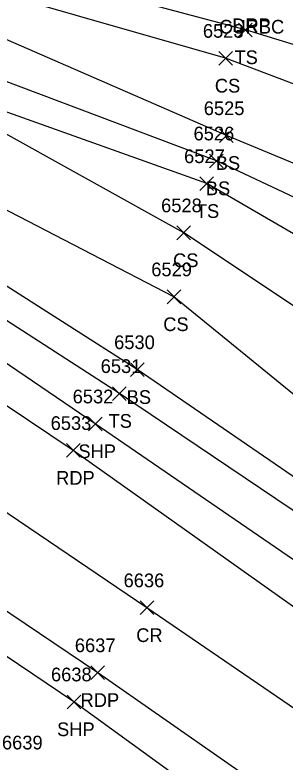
# Model space of a CAD drawing. Extents: x 1505656 to 1508446, y 700805 to 703031.
# Drawn here: x 1507720.3 to 1507759.8, y 701245.9 to 701354.9 of the extents above; entities that cross this region are included whole.
import ezdxf

# ---------------------------------------------------------------- set-up
doc = ezdxf.new("R2010")
doc.units = 0
for name, color, linetype in [('L_A', 7, 'Continuous'), ('L_I', 7, 'Continuous'), ('L_TIC', 7, 'Continuous'), ('LELB', 7, 'Continuous'), ('P_A', 7, 'Continuous'), ('P_I', 7, 'Continuous'), ('P_TIC', 7, 'Continuous'), ('PET', 7, 'Continuous'), ('PRC', 7, 'Continuous'), ('PSP', 7, 'Continuous'), ('R_A', 7, 'Continuous')]:
    doc.layers.add(name, color=color, linetype=linetype)

msp = doc.modelspace()

# ---------------------------------------------------------------- linework, layer by layer
at = {"layer": 'L_TIC'}
for points in [[(1507753.03, 701351.76), (1507755.03, 701353.76)], [(1507755.03, 701351.76), (1507753.03, 701353.76)], [(1507750.13, 701347.61), (1507752.13, 701349.61)], [(1507752.13, 701347.61), (1507750.13, 701349.61)], [(1507750.26, 701336.32), (1507752.26, 701338.32)], [(1507752.26, 701336.32), (1507750.26, 701338.32)], [(1507748.81, 701332.63), (1507750.81, 701334.63)], [(1507750.81, 701332.63), (1507748.81, 701334.63)], [(1507747.38, 701329.31), (1507749.38, 701331.31)], [(1507749.38, 701329.31), (1507747.38, 701331.31)], [(1507744.02, 701322.13), (1507746.02, 701324.13)], [(1507746.02, 701322.13), (1507744.02, 701324.13)], [(1507742.58, 701312.79), (1507744.58, 701314.79)], [(1507744.58, 701312.79), (1507742.58, 701314.79)], [(1507737.23, 701302.16), (1507739.23, 701304.16)], [(1507739.23, 701302.16), (1507737.23, 701304.16)], [(1507734.61, 701298.67), (1507736.61, 701300.67)], [(1507736.61, 701298.67), (1507734.61, 701300.67)]]:
    msp.add_lwpolyline(points, dxfattribs=at)
at = {"layer": 'LELB'}
for points in [[(1507790.41, 701341.61), (1507754.03, 701352.76), (1507708.05, 701364.97), (1507681.85, 701373.12), (1507670.48, 701378.38), (1507653.2, 701386.6), (1507647.55, 701385.55), (1507641.37, 701382.2), (1507637.8, 701373.1), (1507641.82, 701365.1)], [(1507888.34, 701276.55), (1507888.87, 701277.41), (1507874.85, 701282.09), (1507865.24, 701285.97), (1507819.75, 701304.34), (1507789.12, 701315.18), (1507749.81, 701333.63), (1507703.74, 701350.99), (1507669.93, 701363.92), (1507645.02, 701377.64), (1507646.46, 701380.37)], [(1507958.45, 701336.45), (1507943.72, 701322.98), (1507916.13, 701303.87), (1507903.31, 701294.67), (1507892.08, 701289.43), (1507877.87, 701288.47), (1507867.89, 701292.89), (1507821.41, 701310.87), (1507790.62, 701321.07), (1507785.01, 701323.39), (1507751.26, 701337.32), (1507705.7, 701357.18), (1507672.82, 701369.27), (1507646.46, 701380.37)], [(1507888.34, 701276.55), (1507871.44, 701272.97), (1507859.56, 701274.07), (1507818.82, 701298.43), (1507786.1, 701308.48), (1507748.38, 701330.31), (1507702.71, 701346.6), (1507667.51, 701360.57), (1507645.02, 701377.64)], [(1507789.2, 701334.24), (1507751.13, 701348.61), (1507707.11, 701361.23), (1507681.85, 701373.12)], [(1508013.25, 701346.1), (1507984.49, 701324.83), (1507956.47, 701302.43), (1507918.76, 701270.83), (1507904.06, 701248.78), (1507886.68, 701234.44), (1507873.56, 701226.96), (1507860, 701227.91), (1507852, 701227.74), (1507843.18, 701230.27), (1507815.13, 701253.1), (1507771.9, 701280.14), (1507738.23, 701303.16), (1507696.59, 701329.67), (1507663.2, 701353.11), (1507646.46, 701366.45)], [(1508015.05, 701343.61), (1507986.33, 701322.01), (1507960.59, 701298.46), (1507925.28, 701262.85), (1507907.53, 701244.92), (1507889.25, 701230.66), (1507874.35, 701224.63), (1507863.53, 701221.86), (1507853.81, 701222.35), (1507841.84, 701226.62), (1507812.69, 701248.41), (1507769.98, 701276.58), (1507735.61, 701299.67), (1507693.17, 701327.02), (1507661.01, 701349.45), (1507641.82, 701365.1)], [(1507916.99, 701276.14), (1507899.54, 701258.77), (1507881.72, 701245.16), (1507867.45, 701235.85), (1507848.82, 701240.61), (1507819.44, 701259.37), (1507776.79, 701286.76), (1507743.58, 701313.79), (1507698.16, 701337.22), (1507663.2, 701353.11)], [(1507891.9, 701273.68), (1507878.18, 701257.1), (1507870.06, 701251.87), (1507857.54, 701254.89), (1507821.42, 701279.67), (1507798.29, 701290.96), (1507781.81, 701298.69), (1507745.02, 701323.13), (1507702.71, 701346.6)]]:
    msp.add_lwpolyline(points, dxfattribs=at)
at = {"layer": 'P_TIC'}
for points in [[(1507731.08, 701294.24), (1507733.08, 701296.24)], [(1507733.08, 701294.24), (1507731.08, 701296.24)], [(1507727.86, 701290.36), (1507729.86, 701292.36)], [(1507729.86, 701290.36), (1507727.86, 701292.36)], [(1507738.63, 701267.4), (1507740.63, 701269.4)], [(1507740.63, 701267.4), (1507738.63, 701269.4)], [(1507731.44, 701257.92), (1507733.44, 701259.92)], [(1507733.44, 701257.92), (1507731.44, 701259.92)], [(1507727.95, 701253.66), (1507729.95, 701255.66)], [(1507729.95, 701253.66), (1507727.95, 701255.66)]]:
    msp.add_lwpolyline(points, dxfattribs=at)
at = {"layer": 'PET'}
for points in [[(1508337.31, 700875.8), (1508299.12, 700901.22), (1508243.21, 700939.46), (1508171.95, 700987.77), (1508130.48, 701015.52), (1508098, 701037.64), (1508055.47, 701066.53), (1508022.23, 701089.23), (1507988.57, 701112.23), (1507963.26, 701129.32), (1507945.8, 701141.83), (1507902.27, 701172.19), (1507883.2, 701183.96), (1507860.24, 701201.06), (1507835.12, 701217.44), (1507805.58, 701238.78), (1507763.25, 701266.99), (1507728.86, 701291.36), (1507688.43, 701318.43), (1507655.64, 701340.89)], [(1508325.47, 700853.93), (1508286.34, 700880.08), (1508228.39, 700919.42), (1508193.53, 700942.69), (1508162.03, 700964.2), (1508126.36, 700988.76), (1508069.26, 701027.69), (1508039.88, 701046.84), (1507982.91, 701086.28), (1507949.88, 701109.29), (1507927.44, 701124.58), (1507885.02, 701153.86), (1507843.8, 701182.01), (1507811.49, 701204.8), (1507770.51, 701232.43), (1507732.44, 701258.92), (1507681.2, 701293.35)]]:
    msp.add_lwpolyline(points, dxfattribs=at)
at = {"layer": 'PRC'}
msp.add_lwpolyline([(1508330.81, 700865.18), (1508292.58, 700890.76), (1508235.81, 700929.21), (1508200.17, 700953), (1508165.62, 700976.67), (1508123.91, 701005.48), (1508090.88, 701028.02), (1508048, 701056.52), (1508015.22, 701078.96), (1507981.58, 701102.27), (1507956.81, 701119), (1507935.36, 701133.83), (1507892.74, 701162.9), (1507856.87, 701187.72), (1507818.46, 701214.03), (1507776.64, 701243.14), (1507739.63, 701268.4), (1507687.66, 701303.5)], dxfattribs=at)
at = {"layer": 'PSP'}
for points in [[(1508339.2, 700878.52), (1508300.65, 700904.32), (1508290.66, 700911.25), (1508285.71, 700920.13), (1508246.94, 700946.03), (1508214.54, 700968.68), (1508208.31, 700968.43), (1508200.27, 700972.31), (1508174.14, 700990.25), (1508132.47, 701018.55), (1508100.45, 701040.48), (1508057.36, 701069.9), (1508024.07, 701092.52), (1507991.15, 701114.56), (1507965.56, 701132.67), (1507948.13, 701145), (1507904.26, 701176.52), (1507885.27, 701189.48), (1507863.62, 701204.84), (1507839.06, 701222.13), (1507808.57, 701243.06), (1507766.97, 701271.37), (1507732.08, 701295.24), (1507690.9, 701323.18)], [(1508322.11, 700849.23), (1508283.29, 700875.62), (1508225.23, 700915.4), (1508190.18, 700938.93), (1508158.85, 700960.02), (1508133.58, 700977.43), (1508108.68, 700994.35), (1508066.55, 701022.65), (1508035.75, 701043.71), (1507979.02, 701080.76), (1507948.09, 701102.19), (1507924.34, 701119.43), (1507882.16, 701148.7), (1507840.1, 701177.09), (1507807.52, 701199.39), (1507768.58, 701225.94), (1507728.95, 701254.66), (1507678.68, 701288.49)]]:
    msp.add_lwpolyline(points, dxfattribs=at)

# ---------------------------------------------------------------- texts
at = {"layer": 'L_A'}
for s, p in [('TS', (1507752.44, 701347.76)), ('CS', (1507749.57, 701343.61)), ('BS', (1507749.7, 701332.32)), ('BS', (1507748.25, 701328.63)), ('TS', (1507746.79, 701325.31)), ('CS', (1507743.46, 701318.13)), ('CS', (1507742.02, 701308.79)), ('BS', (1507736.67, 701298.16)), ('TS', (1507734.02, 701294.67))]:
    msp.add_text(s, height=2, dxfattribs=at).set_placement(p)
at = {"layer": 'L_I'}
for s, p in [('6523', (1507747.82, 701351.61)), ('6525', (1507747.95, 701340.32)), ('6526', (1507746.45, 701336.63)), ('6527', (1507745.07, 701333.31)), ('6528', (1507741.71, 701326.13)), ('6529', (1507740.27, 701316.79)), ('6530', (1507734.84, 701306.16)), ('6531', (1507732.87, 701302.67)), ('6639', (1507718.43, 701247.72))]:
    msp.add_text(s, height=2, dxfattribs=at).set_placement(p)
at = {"layer": 'P_A'}
for s, p in [('SHP', (1507729.61, 701290.24)), ('RDP', (1507726.35, 701286.36)), ('CR', (1507738.07, 701263.4)), ('RDP', (1507729.93, 701253.92)), ('SHP', (1507726.49, 701249.66))]:
    msp.add_text(s, height=2, dxfattribs=at).set_placement(p)
at = {"layer": 'P_I'}
for s, p in [('6532', (1507728.77, 701298.24)), ('6533', (1507725.55, 701294.36)), ('6636', (1507736.22, 701271.4)), ('6637', (1507729.09, 701261.92)), ('6638', (1507725.6, 701257.66))]:
    msp.add_text(s, height=2, dxfattribs=at).set_placement(p)
at = {"layer": 'R_A'}
for s, p in [('DRP', (1507752.08, 701352.44)), ('CURBC', (1507750.21, 701352.22))]:
    msp.add_text(s, height=2, dxfattribs=at).set_placement(p)

doc.saveas('drawing.dxf')
